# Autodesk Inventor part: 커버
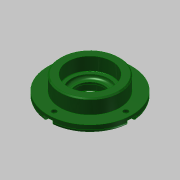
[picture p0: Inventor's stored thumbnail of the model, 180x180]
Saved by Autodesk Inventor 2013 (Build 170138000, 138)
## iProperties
Company: 한국ATC센터
Created: 2016-04
Part Number: 커버
Document SubType Name: Modeling
Designer: mdu
Density: 7.86 g/cm^3
Mass: 351.567 g
Surface Area: 161.165 cm^2
Volume: 44.7286 cm^3
Material: 강철, 연강
Author: mdu
Revision Number: 1
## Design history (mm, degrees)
sketch "스케치1"
  geometry: C1 r 38 at (0, 0); 1 further point
  constraints: 1 centre point, 1 coincident
  dimensions: "d0" = 76 diameter of C1
extrude "돌출1" new body sketch "스케치1" distance "d1" = 7; taper "d2" = 0 deg
sketch "스케치2"
  geometry: C1 r 27 at (0, 0); 1 further point
  constraints: 1 centre point, 1 coincident
  dimensions: "d3" = 54 diameter of C1
extrude "돌출2" join sketch "스케치2" distance "d4" = 13; taper "d5" = 0 deg
sketch "스케치3"
  geometry: C1 r 20 at (0, 0); 1 further point
  constraints: 1 centre point, 1 coincident
  dimensions: "d6" = 40 diameter of C1
extrude "돌출3" join sketch "스케치3" distance "d7" = 5; taper "d8" = 0 deg
hole "구멍1" diameter "d11" = 25; stored, may be unused: countersink angle "d15" = 90 deg, drill point angle "d17" = 118 deg; dims "d9" = 10, "d10" = 10, "d12" = 6, "d13" = 32, "d14" = 8.3, "d16" = 8
hole "구멍2" diameter "d20" = 34; stored, may be unused: countersink angle "d24" = 90 deg, drill point angle "d26" = 0 deg; dims "d18" = 10, "d19" = 10, "d21" = 6, "d22" = 40, "d23" = 12, "d25" = 3
fillet "모깎기2" dims "d34" = 3
fillet "모깎기1" dims "d27" = 0.3
chamfer "모따기1" distance "d28" = 1; stored, may be unused: second distance "d29" = 2, angle "d30" = 45 deg
chamfer "모따기2" distance "d31" = 0.8; stored, may be unused: second distance "d32" = 2, angle "d33" = 30 deg
sketch "스케치4" dims "d35" = 65
  geometry: 3 further points
  constraints: 2 horizontal alignment, 1 coincident, 2 other
hole "구멍3" sketch "스케치4" at (32.5, 0) diameter "d36" = 4.5; stored, may be unused: countersink angle "d40" = 90 deg, drill point angle "d42" = 118 deg; dims "d37" = 6, "d38" = 8, "d39" = 4.4, "d41" = 13
sketch "스케치5"
  geometry: L1 (0, 4)-(5.5, 4); L2 (5.5, 4)-(5.5, -4); L3 (5.5, -4)-(0, -4); L4 (0, -4)-(0, 4); C1 r 2.25 at (0, 0) reference; C2 r 38 at (-32.5, 0) reference; 2 further points
  constraints: 8 end point, 3 horizontal, 2 parallel, 1 perpendicular, 1 tangent, 1 vertical alignment, 1 other
extrude "돌출4" cut sketch "스케치5" stored distance "d47" = 24.5; taper "d48" = 0 deg
node "솔리드1"
pattern_circular "원형 패턴1" dims angle "d44" = 360 deg
pattern_circular "원형 패턴2" dims angle "d50" = 360 deg
node "투영된 루프1"
